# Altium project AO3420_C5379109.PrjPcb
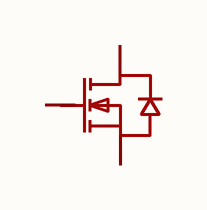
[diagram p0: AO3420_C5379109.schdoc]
1 sheet, 1 parts. Net scope: global (net labels, ports and power ports of the same name join across sheets).

## Sheet AO3420_C5379109.schdoc
size 127 x 101 mm

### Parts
Q?  ao3420_c5379109  [SOT-23-3_L2.9-W1.6-P1.90-LS2.8-BR]  (value not drawn)

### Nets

Not connected (* = marked no-connect by the designer): Q? 1(G) 2(S) 3(D)

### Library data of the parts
Q? = ao3420_c5379109: 数量:1个N沟道;漏源电压(Vdss):20V;连续漏极电流(Id):6A;导通电阻(RDS(on)):18mΩ@4.5V;耗散功率(Pd):1.56W;阈值电压(Vgs(th)):700mV;; Manufacturer: MSKSEMI(美森科); ManufacturerPart: AO3420; AddInBom: yes; ModelId: 89cb27a44ab2466697082bb9fd73a7d0; ModelName: SOT-23-3L_L2.9-W1.6-H1.1-LS2.8-P0.95; ModelTransform: 114.173,110.236,0,90,0,0,0,0,0; Number: 1个N沟道; Drain to Source Voltage: 20V; Current - Continuous Drain(Id): 6A; Pd - Power Dissipation: 1.56W; Gate Threshold Voltage (Vgs(th)): 700mV; Gate Charge(Qg): 5.8nC@4.5V; Input Capacitance(Ciss): 600pF; Reverse Transfer Capacitance (Crss@Vds): 45pF; Output Capacitance(Coss): 70pF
